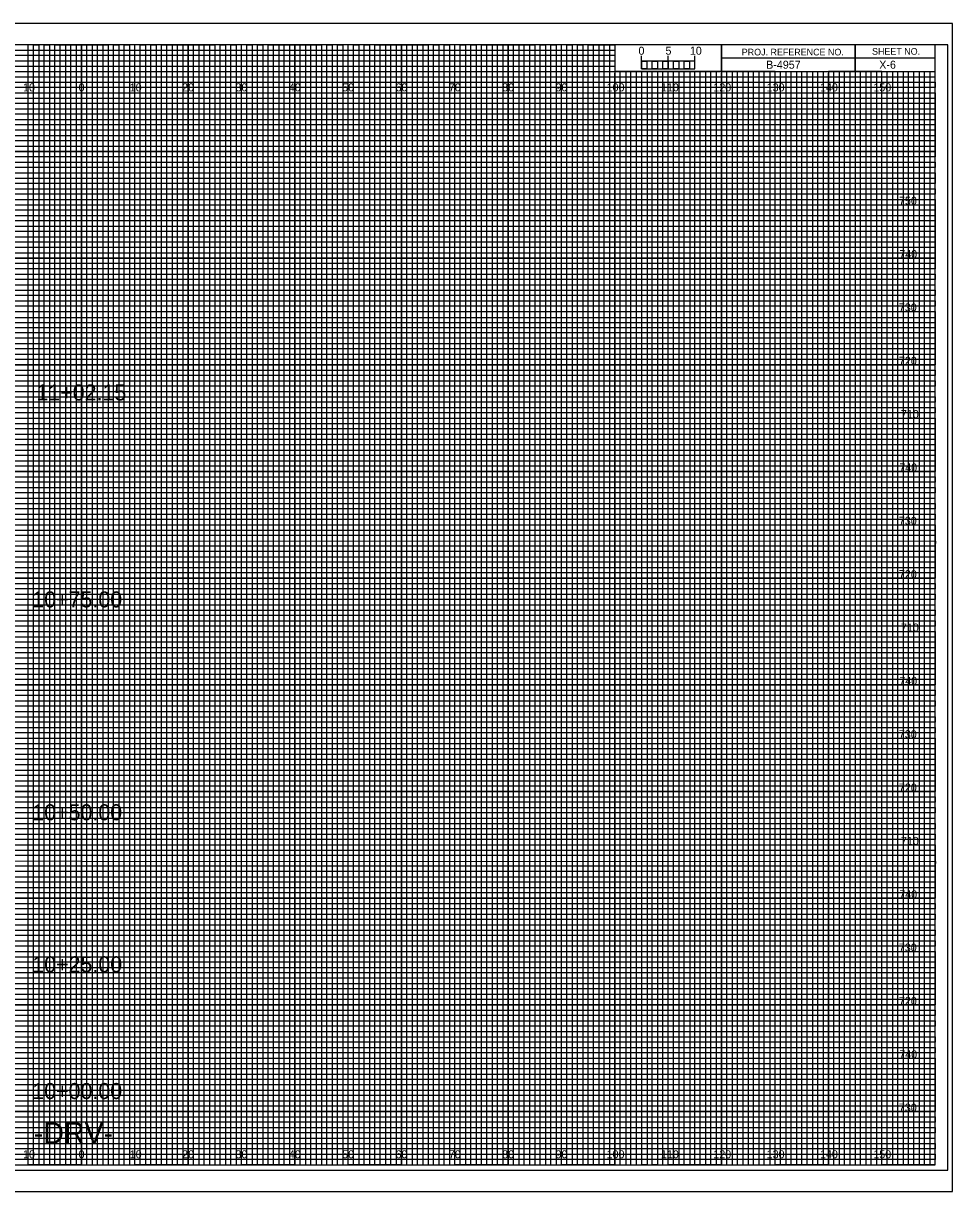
# Model space of a CAD drawing. Extents: x -13 to 323, y -5 to 214.
# Drawn here: x 149.1 to 323.3, y -5 to 214 of the extents above; entities that cross this region are included whole.
import ezdxf

# ---------------------------------------------------------------- set-up
doc = ezdxf.new("R2010")
doc.units = 0
for name, color, linetype in [('Exist Cross Section Cell', 7, 'Continuous'), ('Exist XS Center Line Elevation Label', 7, 'Continuous'), ('Exist XS Ground Line', 7, 'Continuous'), ('Prop XS Alignment Label', 7, 'Continuous'), ('Prop XS Bar Scale Labels', 7, 'Continuous'), ('Prop XS Ditch Slope Text', 7, 'Continuous'), ('Prop XS Ditch Standard Text', 7, 'Continuous'), ('Prop XS Dump Level', 7, 'Continuous'), ('Prop XS EOT Tick Mark', 7, 'Continuous'), ('Prop XS Finish Grade', 7, 'Continuous'), ('Prop XS Finish Grade Earthwork', 7, 'Continuous'), ('Prop XS Finish Grade Pavement', 7, 'Continuous'), ('Prop XS Pvmt Edge Slope', 7, 'Continuous'), ('Prop XS SE Text', 7, 'Continuous'), ('Prop XS Side Slope Text', 7, 'Continuous'), ('Prop XS Subgrade Earthwork', 7, 'Continuous'), ('Sheet Cross Section Scale CELL', 7, 'Continuous')]:
    doc.layers.add(name, color=color, linetype=linetype)

msp = doc.modelspace()

# ---------------------------------------------------------------- linework, layer by layer
at = {"layer": 'Exist XS Center Line Elevation Label'}
for points in [[(145, 0), (155, 0), (155, 210), (165, 210), (165, 0), (175, 0), (175, 210), (185, 210), (185, 0), (195, 0), (195, 210), (205, 210), (205, 0), (215, 0), (215, 210), (225, 210), (225, 0), (235, 0), (235, 210), (245, 210), (245, 0), (255, 0), (255, 210), (259.93, 210), (260, 210), (260, 205), (264.99, 205), (264.99, 0), (275, 0), (275, 205), (285, 205), (285, 0), (295, 0), (295, 205), (305, 205), (305, 0), (315, 0), (315, 205)], [(0, 205), (275, 205)], [(0, 185), (320, 185), (320, 195), (0, 195)], [(0, 165), (320, 165), (320, 175), (0, 175)], [(0, 145), (320, 145), (320, 155), (0, 155)], [(0, 125), (320, 125), (320, 135), (0, 135)], [(0, 105), (320, 105), (320, 115), (0, 115)], [(0, 85), (320, 85), (320, 95), (0, 95)], [(0, 65), (320, 65), (320, 75), (0, 75)], [(0, 45), (320, 45), (320, 55), (0, 55)], [(0, 25), (320, 25), (320, 35), (0, 35)], [(0, 5), (320, 5), (320, 15), (0, 15)]]:
    msp.add_lwpolyline(points, dxfattribs=at)
at = {"layer": 'Exist XS Ground Line'}
for p, q in [((150, 210), (140, 210)), ((150, 0), (150, 210)), ((170, 210), (160, 210)), ((160, 210), (160, 0)), ((170, 0), (170, 210)), ((190, 210), (180, 210)), ((180, 210), (180, 0)), ((190, 0), (190, 210)), ((210, 210), (200, 210)), ((200, 210), (200, 0)), ((210, 0), (210, 210)), ((230, 210), (220, 210)), ((220, 210), (220, 0)), ((230, 0), (230, 210)), ((250, 210), (240, 210)), ((240, 210), (240, 0)), ((250, 0), (250, 210)), ((260, 210), (260, 0)), ((270, 0), (270, 205)), ((290, 205), (280, 205)), ((280, 205), (280, 0)), ((290, 0), (290, 205)), ((310, 205), (300, 205)), ((300, 205), (300, 0)), ((310, 0), (310, 205)), ((160, 0), (150, 0)), ((180, 0), (170, 0)), ((200, 0), (190, 0)), ((220, 0), (210, 0)), ((240, 0), (230, 0)), ((260, 0), (250, 0)), ((280, 0), (270, 0)), ((300, 0), (290, 0)), ((320, 0), (310, 0)), ((320, 0), (320, 0))]:
    msp.add_line(p, q, dxfattribs=at)
for points in [[(0, 200), (320, 200), (320, 190), (0, 190)], [(0, 180), (320, 180), (320, 170), (0, 170)], [(0, 160), (320, 160), (320, 150), (0, 150)], [(0, 140), (320, 140), (320, 130), (0, 130)], [(0, 120), (320, 120), (320, 110), (0, 110)], [(0, 100), (320, 100), (320, 90), (0, 90)], [(0, 80), (320, 80), (320, 70), (0, 70)], [(0, 60), (320, 60), (320, 50), (0, 50)], [(0, 40), (320, 40), (320, 30), (0, 30)], [(0, 20), (320, 20), (320, 10), (0, 10)]]:
    msp.add_lwpolyline(points, dxfattribs=at)
at = {"layer": 'Prop XS Ditch Slope Text'}
msp.add_lwpolyline([(-10.8, -1), (322.4, -1), (322.4, 210), (-10.8, 210)], close=True, dxfattribs=at)
at = {"layer": 'Prop XS Ditch Standard Text'}
msp.add_lwpolyline([(-13.4, -5), (323.3, -5), (323.3, 214), (-13.4, 214)], close=True, dxfattribs=at)
at = {"layer": 'Prop XS Dump Level'}
for p, q in [((305, 210), (305, 205)), ((305, 205), (305, 210)), ((280, 207.5), (280, 205)), ((320, 207.49), (280, 207.49)), ((280, 205), (320, 205))]:
    msp.add_line(p, q, dxfattribs=at)
for points in [[(320, 210), (0, 210), (0, 0), (320, 0)], [(280, 210), (260, 210), (260, 205.03), (280, 205.03)], [(320, 210), (280, 210), (280, 205), (320, 205)]]:
    msp.add_lwpolyline(points, close=True, dxfattribs=at)
at = {"layer": 'Prop XS Finish Grade Earthwork'}
for p, q in [((150, 0), (150, 210)), ((160, 0), (160, 210)), ((170, 0), (170, 210)), ((180, 0), (180, 210)), ((190, 0), (190, 210)), ((200, 0), (200, 210)), ((210, 0), (210, 210)), ((220, 0), (220, 210)), ((230, 0), (230, 210)), ((240, 0), (240, 210)), ((250, 0), (250, 210)), ((260, 0), (260, 204.69)), ((270, 0), (270, 204.69)), ((280, 0), (280, 204.69)), ((290, 0), (290, 204.69)), ((300, 0), (300, 204.69)), ((310, 0), (310, 204.69)), ((0, 200), (320, 200)), ((0, 190), (320, 190)), ((0, 180), (320, 180)), ((0, 170), (320, 170)), ((0, 160), (320, 160)), ((0, 150), (320, 150)), ((0, 140), (320, 140)), ((0, 130), (320, 130)), ((0, 120), (320, 120)), ((0, 110), (320, 110)), ((0, 100), (320, 100)), ((0, 90), (320, 90)), ((0, 80), (320, 80)), ((0, 70), (320, 70)), ((0, 60), (320, 60)), ((0, 50), (320, 50)), ((0, 40), (320, 40)), ((0, 30), (320, 30)), ((0, 20), (320, 20)), ((0, 10), (320, 10))]:
    msp.add_line(p, q, dxfattribs=at)
at = {"layer": 'Prop XS SE Text'}
for p, q in [((0, 209), (260, 209)), ((260, 209), (260, 207.98)), ((260, 207.98), (0, 207.98)), ((0, 207), (260, 207)), ((260, 205.89), (0, 205.89)), ((260, 207), (260, 205.89)), ((0, 204), (320, 204))]:
    msp.add_line(p, q, dxfattribs=at)
for points in [[(0, 203), (270, 203), (320, 203), (320, 202), (0, 202)], [(0, 201), (320, 201), (320, 199), (0, 199)], [(0, 198), (320, 198), (320, 197), (0, 196.98)], [(0, 196), (320, 196), (320, 194), (0, 194)], [(0, 193), (320, 193), (320, 192), (0, 192)], [(0, 191), (320, 191), (320, 189), (0, 189)], [(0, 188), (320, 188), (320, 187), (0, 187)], [(0, 186), (320, 186), (320, 184), (0, 184)], [(0, 183), (320, 183), (320, 182), (0, 182)], [(0, 181), (320, 181), (320, 179), (0, 179)], [(0, 178), (320, 178), (320, 177), (0, 177)], [(0, 176), (320, 176), (320, 173.95), (320, 173), (320, 172), (0, 172)], [(0, 174), (320, 174), (320, 173), (0, 173)], [(0, 171), (320, 171), (320, 169), (0, 169.03)], [(0, 169.03), (320, 169), (320, 168), (0, 168)], [(0, 167), (320, 167), (320, 166), (0, 166)], [(0, 164), (320, 164), (320, 163), (0, 163)], [(0, 162), (320, 162), (320, 161), (0, 161)], [(-0.07, 158.89), (320, 158.89), (320, 157.88), (-0.07, 157.88)], [(0, 157), (320, 157), (320, 156), (0, 156)], [(0, 154), (320, 154), (320, 153), (0, 153)], [(0, 152), (320, 152), (320, 151), (0, 151)], [(0, 149), (320, 149), (320, 148), (0, 148)], [(0, 147), (320, 147), (320, 146), (0, 146)], [(0, 144), (320, 144), (320, 143), (0, 143)], [(0, 142), (320, 142), (320, 141), (0, 141)], [(0, 139), (320, 139), (319.99, 137.98), (0, 138)], [(0, 137), (320, 137), (320, 136), (0, 136)], [(0, 134), (320, 134), (320, 133), (0, 133)], [(0, 132), (320, 132), (320, 131), (0, 131)], [(0, 129), (320, 129), (320, 128), (0, 128)], [(0, 127), (320, 127), (320, 126), (0, 126)], [(0, 124), (320, 124), (320, 123), (0, 123)], [(0, 122), (320, 122), (320, 121), (0, 121)], [(0, 119), (320, 119), (320, 118), (0, 118)], [(0, 116.99), (320.07, 116.91), (320, 116), (0, 116)], [(0, 114), (320, 114), (320, 113), (0, 113)], [(0, 112), (320, 112), (320, 111), (0, 111)], [(0, 109), (320, 109), (320, 108), (0, 108)], [(0, 107), (320, 107), (320, 106), (0, 106)], [(0, 104), (320, 104), (320, 103), (0, 103)], [(0, 102), (320, 102), (320, 101), (0, 101)], [(0, 99), (320, 99), (320, 98), (0, 98)], [(0, 97), (320, 97), (320, 96), (0, 96)], [(0, 94), (320, 94), (320, 93), (0, 93)], [(0, 92), (320, 92), (320, 91), (0, 91)], [(0, 89), (320, 89), (320, 88), (0, 88)], [(0, 87), (320, 87), (320, 86), (0, 86)], [(0, 84), (320, 84), (320, 83), (0, 83)], [(0, 82), (320, 82), (320, 81), (0, 81)], [(0, 79), (320, 79), (319.99, 77.98), (0, 78)], [(0, 77), (320, 77), (320, 76), (0, 76)], [(0, 74), (320, 74), (320, 73), (0, 73)], [(0, 72), (320, 72), (320, 71), (0, 71)], [(0, 69), (320, 69), (320, 68), (0, 68)], [(0, 67), (320, 67), (320, 66), (0, 66)], [(0, 64), (320, 64), (320, 63), (0, 63)], [(0, 62), (320, 62), (320, 61), (0, 61)], [(0, 59), (320, 59), (320, 58), (0, 58)], [(0, 56.99), (320.07, 56.91), (320, 56), (0, 56)], [(0, 54), (320, 54), (320, 53), (0, 53)], [(0, 52), (320, 52), (320, 51), (0, 51)], [(0, 49), (320, 49), (320, 48), (0, 48)], [(0, 47), (320, 47), (320, 46), (0, 46)], [(0, 44), (320, 44), (320, 43), (0, 43)], [(0, 42), (320, 42), (320, 41), (0, 41)], [(0, 39), (320, 39), (320, 38), (0, 38)], [(0, 37), (320, 37), (320, 36), (0, 36)], [(0, 34), (320, 34), (320, 33), (0, 33)], [(0, 32), (320, 32), (320, 31), (0, 31)], [(0, 29), (320, 29), (320, 28), (0, 28)], [(0, 27), (320, 27), (320, 26), (0, 26)], [(0, 24), (320, 24), (320, 23), (0, 23)], [(0, 22), (320, 22), (320, 21), (0, 21)], [(0, 19), (320, 19), (320, 18), (0, 18)], [(0, 17), (320, 17), (320, 16), (0, 16)], [(0, 14), (320, 14), (320, 13), (0, 13)], [(0, 12), (320, 12), (320, 11), (0, 11)], [(0, 9), (320, 9), (320, 8), (0, 8)], [(0, 7), (320, 7), (320, 6), (0, 6)], [(0, 4), (320, 4), (320, 3), (0, 3)], [(0, 2), (320, 2), (320, 1), (0, 1)]]:
    msp.add_lwpolyline(points, dxfattribs=at)
at = {"layer": 'Prop XS Side Slope Text'}
for p, q in [((267, 205), (266.01, 205)), ((266.01, 205), (266.01, 0)), ((267, 0), (267, 205)), ((269, 205), (268, 205)), ((268, 205), (268, 0)), ((269, 0), (269, 205)), ((266.01, 0), (265, 0)), ((268, 0), (267, 0))]:
    msp.add_line(p, q, dxfattribs=at)
for points in [[(150, 0), (151, 0), (151, 210), (152, 210), (152, 0)], [(152, 0), (153, 0), (153, 210), (154, 210), (154, 0)], [(155, 0), (156, 0), (156, 210), (157, 210), (157, 0)], [(157, 0), (158, 0), (158, 210), (159, 210), (159, 0)], [(160, 0), (161, 0), (161, 210), (162, 210), (162, 0)], [(162, 0), (163, 0), (163, 210), (164, 210), (164, 0)], [(165, 0), (166, 0), (166, 210), (167, 210), (167, 0)], [(167, 0), (168, 0), (168, 210), (169, 210), (169, 0)], [(170, 0), (171, 0), (171, 210), (172, 210), (172, 0)], [(172, 0), (173, 0), (173, 210), (174, 210), (174, 0)], [(175, 0), (176, 0), (176, 210), (177, 210), (177, 0)], [(177, 0), (178, 0), (178, 210), (179, 210), (179, 0)], [(180, 0), (181, 0), (181, 210), (182, 210), (182, 0)], [(182, 0), (183, 0), (183, 210), (184, 210), (184, 0)], [(185, 0), (186, 0), (186, 210), (187, 210), (187, 0)], [(187, 0), (188, 0), (188, 210), (189, 210), (189, 0)], [(190, 0), (191, 0), (191, 210), (192, 210), (192, 0)], [(192, 0), (193, 0), (193, 210), (194, 210), (194, 0)], [(195, 0), (196, 0), (196, 210), (197, 210), (197, 0)], [(197, 0), (198, 0), (198, 210), (199, 210), (199, 0)], [(200, 0), (201, 0), (201, 210), (202, 210), (202, 0)], [(202, 0), (203, 0), (203, 210), (204, 210), (204, 0)], [(205, 0), (206, 0), (206, 210), (207, 210), (207, 0)], [(207, 0), (208, 0), (208, 210), (209, 210), (209, 0)], [(210, 0), (211, 0), (211, 210), (212, 210), (212, 0)], [(212, 0), (213, 0), (213, 210), (214, 210), (214, 0)], [(215, 0), (216, 0), (216, 210), (217, 210), (217, 0)], [(217, 0), (218, 0), (218, 210), (219, 210), (219, 0)], [(220, 0), (221, 0), (221, 210), (222, 210), (222, 0)], [(222, 0), (223, 0), (223, 210), (224, 210), (224, 0)], [(225, 0), (226, 0), (226, 210), (227, 210), (227, 0)], [(227, 0), (228, 0), (228, 210), (229, 210), (229, 0)], [(230, 0), (231, 0), (231, 210), (232, 210), (232, 0)], [(232, 0), (233, 0), (233, 210), (234, 210), (234, 0)], [(235, 0), (236, 0), (236, 210), (237, 210), (237, 0)], [(237, 0), (238, 0), (238, 210), (239, 210), (239, 0)], [(240, 0), (241, 0), (241, 210), (242, 210), (242, 0)], [(242, 0), (243, 0), (243, 210), (244, 210), (244, 0)], [(245, 0), (246, 0), (246, 210), (247, 210), (247, 0)], [(247, 0), (248, 0), (248, 210), (249, 210), (249, 0)], [(250, 0), (251, 0), (251, 210), (252, 210), (252, 0)], [(252, 0), (253, 0), (253, 210), (254, 210), (254, 0)], [(255, 0), (256, 0), (256, 210), (257, 210), (257, 0)], [(257, 0), (258, 0), (258, 210), (259, 210), (259, 0)], [(260, 0), (261, 0), (261, 205), (262.02, 205), (262.02, 0)], [(262, 0), (263, 0), (263, 205), (263.99, 205), (263.99, 0)], [(270, 0), (270.98, 0), (270.98, 205), (272, 205), (272, 0)], [(272, 0), (273, 0), (273, 205), (274.05, 205), (274.05, 0)], [(275, 0), (276, 0), (276, 205), (277, 205), (277, 0)], [(277, 0), (278, 0), (278, 205), (279, 205), (279, 0)], [(280, 0), (281, 0), (281, 205), (282, 205), (282, 0)], [(282, 0), (283, 0), (283, 205), (284, 205), (284, 0)], [(285, 0), (286, 0), (286, 205), (287, 205), (287, 0)], [(287, 0), (288, 0), (288, 205), (289, 205), (289, 0)], [(290, 0), (291, 0), (291, 205), (292, 205), (292, 0)], [(292, 0), (293, 0), (293, 205), (294, 205), (294, 0)], [(295, 0), (296, 0), (296, 205), (297, 205), (297, 0)], [(297, 0), (298, 0), (298, 205), (299, 205), (299, 0)], [(300, 0), (301, 0), (301, 205), (302, 205), (302, 0)], [(302, 0), (303, 0), (303, 205), (304, 205), (304, 0)], [(305, 0), (306, 0), (306, 205), (307, 205), (307, 0)], [(307, 0), (308, 0), (308, 205), (309, 205), (309, 0)], [(310, 0), (311, 0), (311, 205), (312, 205), (312, 0)], [(312, 0), (313, 0), (313, 205), (314, 205), (314, 0)], [(315, 0), (316, 0), (316, 205), (317, 205), (317, 0)], [(317, 0), (318, 0), (318, 205), (319, 205), (319, 0)]]:
    msp.add_lwpolyline(points, dxfattribs=at)
at = {"layer": 'Prop XS Subgrade Earthwork'}
for p, q in [((323.3, 214), (-13.4, 214)), ((-13.4, -5), (323.3, -5))]:
    msp.add_line(p, q, dxfattribs=at)
at = {"layer": 'Sheet Cross Section Scale CELL'}
for p, q in [((265, 205.49), (265, 207.9)), ((265, 206.9), (265, 207.9)), ((270, 205.49), (270, 207.9)), ((275, 205.49), (275, 207.9)), ((275, 206.9), (275, 207.9))]:
    msp.add_line(p, q, dxfattribs=at)
for points in [[(275, 206.9), (265, 206.9), (265, 205.49), (275, 205.49)], [(265, 206.9), (266, 206.9), (266, 205.49), (265, 205.49)], [(267, 206.9), (268, 206.9), (268, 205.49), (267, 205.49)], [(269, 206.9), (270, 206.9), (270, 205.49), (269, 205.49)], [(271, 206.9), (272, 206.9), (272, 205.49), (271, 205.49)], [(273, 206.9), (274, 206.9), (274, 205.49), (273, 205.49)]]:
    msp.add_lwpolyline(points, close=True, dxfattribs=at)

# ---------------------------------------------------------------- texts
at = {"layer": 'Exist Cross Section Cell'}
for s, p in [('10', (149.04, 201.25)), ('0', (159.45, 201.25)), ('0', (159.45, 201.25)), ('10', (169.04, 201.25)), ('20', (178.86, 201.25)), ('30', (188.86, 201.25)), ('40', (198.86, 201.25)), ('50', (208.86, 201.25)), ('60', (218.86, 201.25)), ('70', (228.86, 201.25)), ('80', (238.86, 201.25)), ('90', (248.86, 201.25)), ('100', (258.44, 201.25)), ('110', (268.62, 201.25)), ('120', (278.44, 201.25)), ('130', (288.44, 201.25)), ('140', (298.44, 201.25)), ('150', (308.44, 201.25)), ('10', (149.04, 1.25)), ('0', (159.45, 1.25)), ('0', (159.45, 1.25)), ('10', (169.04, 1.25)), ('20', (178.86, 1.25)), ('30', (188.86, 1.25)), ('40', (198.86, 1.25)), ('50', (208.86, 1.25)), ('60', (218.86, 1.25)), ('70', (228.86, 1.25)), ('80', (238.86, 1.25)), ('90', (248.86, 1.25)), ('100', (258.44, 1.25)), ('110', (268.62, 1.25)), ('120', (278.44, 1.25)), ('130', (288.44, 1.25)), ('140', (298.44, 1.25)), ('150', (308.44, 1.25))]:
    msp.add_text(s, height=1.5, dxfattribs=at).set_placement(p)
at = {"layer": 'Prop XS Alignment Label'}
msp.add_text('-DRV-', height=4, dxfattribs=at).set_placement((151.06, 4))
at = {"layer": 'Prop XS Bar Scale Labels'}
for s, p in [('5', (269.47, 208.12)), ('10', (274.04, 208.12))]:
    msp.add_text(s, height=1.5, dxfattribs=at).set_placement(p)
at = {"layer": 'Prop XS Dump Level'}
for s, p in [('PROJ. REFERENCE NO.', (283.77, 207.99)), ('SHEET NO.', (308.19, 208.12))]:
    msp.add_text(s, height=1.25, dxfattribs=at).set_placement(p)
at = {"layer": 'Prop XS EOT Tick Mark'}
msp.add_text('X-6', height=1.5, dxfattribs=at).set_placement((309.54, 205.5))
at = {"layer": 'Prop XS Finish Grade'}
for s, p in [('750', (313.25, 180)), ('740', (313.3, 170)), ('730', (313.22, 160)), ('720', (313.23, 150)), ('710', (313.61, 140)), ('740', (313.3, 130)), ('730', (313.22, 120)), ('720', (313.23, 110)), ('710', (313.61, 100)), ('740', (313.3, 90)), ('730', (313.22, 80)), ('720', (313.23, 70)), ('710', (313.61, 60)), ('740', (313.3, 50)), ('730', (313.22, 40)), ('720', (313.23, 30)), ('740', (313.3, 20)), ('730', (313.22, 10))]:
    msp.add_text(s, height=1.5, dxfattribs=at).set_placement(p)
at = {"layer": 'Prop XS Finish Grade Pavement'}
msp.add_text('B-4957', height=1.5, dxfattribs=at).set_placement((288.34, 205.5))
at = {"layer": 'Prop XS Pvmt Edge Slope'}
for s, p in [('11+02.15', (151.54, 143.31)), ('10+75.00', (150.77, 104.52)), ('10+50.00', (150.77, 64.61)), ('10+25.00', (150.77, 36.11)), ('10+00.00', (150.77, 12.36))]:
    msp.add_text(s, height=3, dxfattribs=at).set_placement(p)
at = {"layer": 'Sheet Cross Section Scale CELL'}
msp.add_text('0', height=1.5, dxfattribs=at).set_placement((264.41, 208.12))

doc.saveas('drawing.dxf')
